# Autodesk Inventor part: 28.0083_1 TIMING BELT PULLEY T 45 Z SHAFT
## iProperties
Created: 2007-06
Part Number: 28.0083_1 TIMING BELT PULLEY T 45 Z SHAFT
Document SubType Name: Modeling
Designer: Andy Moles
Material: Steel
Mass: 112.874 g
Surface Area: 49.3937 cm^2
Volume: 14.3788 cm^3
Density: 7.85 g/cm^3
Author: Andy Moles
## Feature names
1. Extrusion1
2. Extrusion2
3. Hole1
4. Chamfer1
5. Extrusion3
